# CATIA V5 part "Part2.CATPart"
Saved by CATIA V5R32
Part number: Part2
Bounding box of the stored display mesh (mm): x -29.913 to 29.913, y -29.913 to 29.913, z -89.119 to 0
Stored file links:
  D:\PROJECTS\Project 2022\CATIA V5 6R 2022\Resources\Part Files\c12_catia_v5_6r2022_prt\c12_catia_v5-6r2022 figr_12-35\Part2.CATPart
  C:\CATIA-V5R13-manuscript\catia-v5r13-solid-models-090204\c11\Figure 11-35\Figure 11-35.CATProduct
  D:\PROJECTS\Project 2022\CATIA V5 6R 2022\Resources\Part Files\c12_catia_v5_6r2022_prt\c12_catia_v5-6r2022 figr_12-35\Base.CATPart
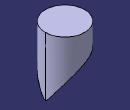
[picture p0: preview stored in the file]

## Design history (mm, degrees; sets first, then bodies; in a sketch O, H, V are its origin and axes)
Set1
  DatumSurface1: linked copy from another document
Body1 (main body)
  Sketch1 on xy-plane, origin (0, 0, 0), H (1, 0, 0), V (0, 1, 0)
    circle A1 centre (0, 0) radius 29.9132
  Pad1: profile Sketch1, direction (0, 0, 1), up to face of DatumSurface1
